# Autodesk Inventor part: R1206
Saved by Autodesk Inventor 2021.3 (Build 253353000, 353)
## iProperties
Created: 2023-03
Part Number: R1206
Material: Generic
Document SubType Name: Modeling
Designer: AdminForWorker
Density: 1 g/cm^3
Appearance: Default
Title: R1206
Author: AdminForWorker
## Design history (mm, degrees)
feature "Body1"
body "Solid1"
